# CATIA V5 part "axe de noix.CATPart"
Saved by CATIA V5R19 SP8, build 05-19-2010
Part number: axe de noix
Revision: ANY
Definition: UNKNOWN
Nomenclature: axe de noix
Source: Unknown
Bounding box of the stored display mesh (mm): x 0 to 15.4, y -3 to 3, z -3 to 3
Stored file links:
  D:\Documents\1_Travail\1 - ac-limoges.fr\ac-limoges.fr\Emmanuel Maynard - STI2D_Turgot\2 -2I2D\2_SEQUENCE_Serrure_Biométrique\5-Spé_ITEC\Serrure_Bio_Eleve\axe de noix.CATPart
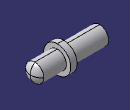
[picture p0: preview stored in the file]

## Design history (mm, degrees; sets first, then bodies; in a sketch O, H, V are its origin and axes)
Body1 "Dôme1" (main body)
  Solid1: solid without history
